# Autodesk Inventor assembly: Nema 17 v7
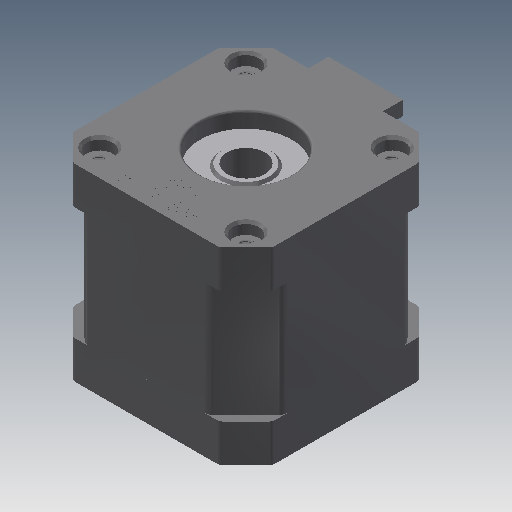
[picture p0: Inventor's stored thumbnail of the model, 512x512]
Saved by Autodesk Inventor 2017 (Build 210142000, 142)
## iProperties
Created: 2018-08
Part Number: Nema 17 v7
Document SubType Name: Assembly
Designer: JK
Author: JK
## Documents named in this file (4)
- C:\Users\JK\Documents\Inventor\BioExtruder\Nema 17 v7.iam
- C:\Users\JK\Documents\Inventor\BioExtruder\Nema Middle.ipt
- C:\Users\JK\Documents\Inventor\BioExtruder\Nema bottom.ipt
- C:\Users\JK\Documents\Inventor\BioExtruder\Nema Top.ipt
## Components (3 placed, 3 different names)
1. Nema Middle:1
2. Nema bottom:1
3. Nema Top:1
